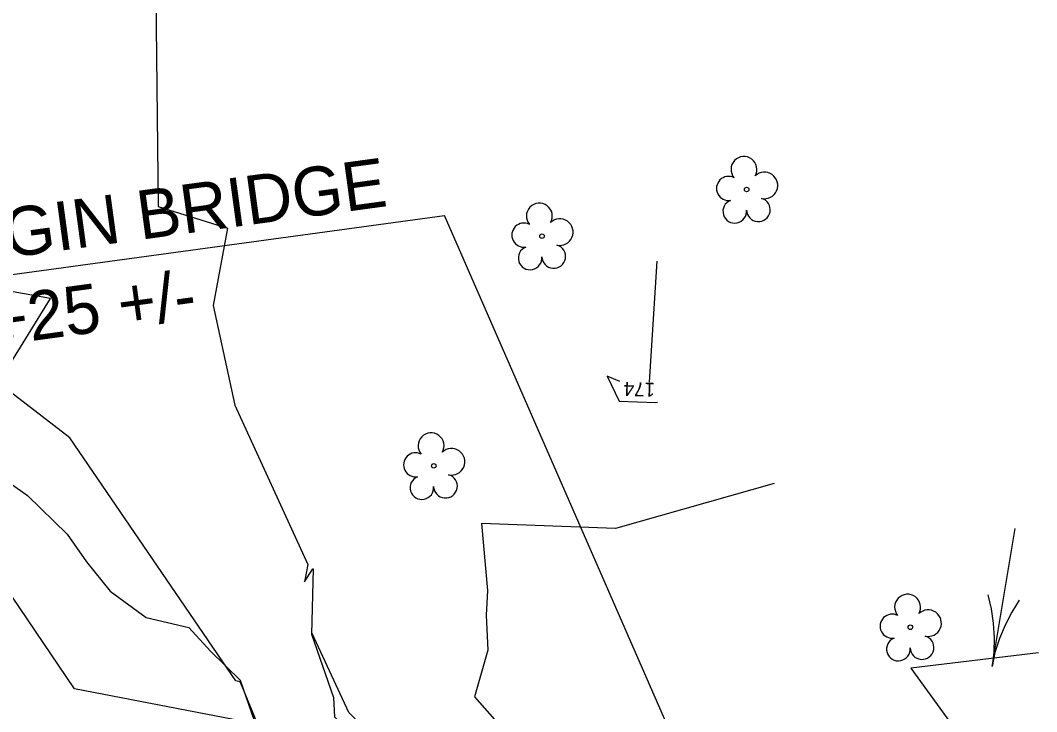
# Model space of a CAD drawing. Extents: x 2086416 to 2115205, y 575507 to 632762.
# Drawn here: x 2111920.5 to 2112066, y 581787.3 to 581886.3 of the extents above; entities that cross this region are included whole.
import ezdxf

# ---------------------------------------------------------------- set-up
doc = ezdxf.new("R2010")
doc.units = 0
for name, color, linetype in [('DTM Contours Minor', 7, 'Continuous'), ('DTM Contours Minor Text', 7, 'Continuous'), ('Exist Hydro River Flow Arrow CELL', 7, 'Continuous'), ('Exist Hydro Stream or Body of Water', 7, 'Continuous'), ('Exist Vegetation Tree CELL', 7, 'Continuous'), ('Prop Horizontal Alignment Station Label', 7, 'Continuous')]:
    doc.layers.add(name, color=color, linetype=linetype)

# ---------------------------------------------------------------- blocks, each defined once
blk = doc.blocks.new('EXIST VEGETATION TREE')
at = {"layer": 'Exist Vegetation Tree CELL'}
blk.add_line((0, 0), (0, 0), dxfattribs=at)
blk.add_circle((0, 0), 0.00652, dxfattribs=at)
for centre, radius, start, end in [((-0.0077, 0.0575), 0.0371, 330.1651, 219.7134), ((-0.0521, 0.0031), 0.0345, 62.6636, 279.3457), ((0.051, 0.0118), 0.038, 257.1011, 134.1999), ((0.0335, -0.058), 0.034, 181.2822, 74.56), ((-0.0341, -0.0624), 0.0338, 111.5671, 6.231)]:
    blk.add_arc(centre, radius, start, end, dxfattribs=at)

msp = doc.modelspace()

# ---------------------------------------------------------------- linework, layer by layer
at = {"layer": 'DTM Contours Minor'}
for points in [[(2111986.57, 581903.53), (2111939.89, 581889.69), (2111940.22, 581859.65), (2111950.16, 581856.54), (2111948.11, 581845.47), (2111951.21, 581831.21), (2111961.67, 581808.41), (2111961.19, 581805.94), (2111962.39, 581807.77), (2111962.43, 581807.8), (2111962.19, 581798.43), (2111965.32, 581789.35), (2111965.47, 581786.59), (2111973.88, 581778.03), (2111977.11, 581774.63), (2111980.39, 581770.88), (2111987.46, 581769.35), (2111990.76, 581766.29)], [(2112011.63, 581851.85), (2112010.53, 581834.49)], [(2111965.16, 581748.51), (2111970.69, 581749.86), (2111976.47, 581749.51), (2111981.91, 581752.5), (2111983.32, 581753.31), (2111982.36, 581755.79), (2111980.14, 581760.97), (2111975.64, 581761.52), (2111969.46, 581763.24), (2111967.22, 581769.18), (2111966.98, 581769.81), (2111965.9, 581771.13), (2111955.64, 581782.68), (2111952.51, 581790.39), (2111952, 581791.62), (2111951.36, 581791.75), (2111927.6, 581826.56), (2111917.31, 581834.4), (2111924.82, 581846.5), (2111912.24, 581848.72), (2111889.78, 581833.71), (2111886.95, 581833.16), (2111879.3, 581820.3)], [(2112006.32, 581834.62), (2112004.52, 581835.36), (2112006.26, 581831.8), (2112011.5, 581831.6), (2112011.73, 581831.66)], [(2112028.44, 581819.99), (2112005.74, 581813.55), (2111986.52, 581814.28), (2111987.37, 581804.69), (2111987.18, 581801.17), (2111987.42, 581796.12), (2111985.53, 581789.47), (2111990.87, 581783.42)], [(2111872.65, 581745.71), (2111876.29, 581746.03), (2111892.64, 581747.28), (2111896.68, 581747.18), (2111903.16, 581748.2), (2111906.44, 581747.76), (2111910.2, 581745.85), (2111927.92, 581748.91), (2111939.7, 581750.88), (2111951.09, 581752.85), (2111957.32, 581753.9), (2111972.19, 581756.27), (2111962.31, 581758.92), (2111961.55, 581761.08), (2111960.4, 581763.71), (2111955.81, 581769.32), (2111952.04, 581783.78), (2111951.03, 581786.21), (2111928.27, 581790.63), (2111917.03, 581807.1), (2111909.85, 581812.57), (2111903.37, 581811.31)], [(2112066.28, 581795.74), (2112048, 581793.55), (2112061.06, 581775.54), (2112061.72, 581774.65), (2112054.08, 581764.55), (2112060.15, 581764.51), (2112053.46, 581749.4), (2112053.37, 581746.7), (2112053.2, 581742.71), (2112053.57, 581738.55), (2112056.36, 581729.73), (2112057.47, 581723.04), (2112058.24, 581720.01), (2112063.98, 581709.95), (2112064.08, 581709.79), (2112064.18, 581709.63), (2112064.52, 581708.58), (2112068.43, 581698.96)]]:
    msp.add_lwpolyline(points, dxfattribs=at)
at = {"layer": 'Exist Hydro River Flow Arrow CELL'}
for p, q in [((2112059.64, 581793.82), (2112062.93, 581813.55)), ((2112059.03, 581804.06), (2112059.49, 581802.07)), ((2112061.28, 581803.68), (2112061.28, 581803.68)), ((2112063.54, 581803.31), (2112062.45, 581801.57)), ((2112059.49, 581802.07), (2112059.8, 581800.01)), ((2112062.45, 581801.57), (2112061.5, 581799.73)), ((2112059.8, 581800.01), (2112059.93, 581797.93)), ((2112061.5, 581799.73), (2112060.7, 581797.8)), ((2112059.93, 581797.93), (2112059.9, 581795.85)), ((2112060.7, 581797.8), (2112060.05, 581795.83)), ((2112059.9, 581795.85), (2112059.64, 581793.82)), ((2112060.05, 581795.83), (2112059.64, 581793.82))]:
    msp.add_line(p, q, dxfattribs=at)
at = {"layer": 'Exist Hydro Stream or Body of Water'}
for points in [[(2111914.05, 581823.59), (2111921.52, 581818.26), (2111927.21, 581812.76), (2111929.98, 581808.81), (2111933.37, 581804.58), (2111938.52, 581800.81), (2111944.63, 581799.41), (2111947.75, 581796), (2111952.02, 581791.78)], [(2112059.94, 581700.98), (2112062.59, 581707.22), (2112055.44, 581716.4), (2112054.67, 581722.41), (2112052.26, 581739.2), (2112051.84, 581739.05), (2112049.8, 581742.56), (2112050.11, 581752.77), (2112039.24, 581754.19), (2112006.97, 581748.92), (2112002.42, 581748.72), (2111999.87, 581752.29), (2111991.63, 581772.37), (2111979.18, 581775.68), (2111967.53, 581787.22), (2111962.27, 581798.52)], [(2111979.59, 581759.49), (2111969.33, 581762.97), (2111966.87, 581769.78), (2111955.26, 581782.47), (2111952.02, 581791.78)]]:
    msp.add_lwpolyline(points, dxfattribs=at)
at = {"layer": 'Prop Horizontal Alignment Station Label'}
for p in [(2111851.3, 581840.64), (2112041.04, 581721.6)]:
    msp.add_line(p, (2111981.25, 581858.37), dxfattribs=at)

# ---------------------------------------------------------------- block references
at = {"layer": 'Exist Vegetation Tree CELL', "xscale": 50, "yscale": 50}
for p in [(2112024.5, 581862.08), (2111995.2, 581855.4), (2111979.7, 581822.52), (2112047.93, 581799.42)]:
    msp.add_blockref('EXIST VEGETATION TREE', p, dxfattribs=at)

# ---------------------------------------------------------------- texts
at = {"layer": 'DTM Contours Minor Text'}
msp.add_text('174', height=2, rotation=178.2142, dxfattribs=at).set_placement((2112011.4, 581834.4))
at = {"layer": 'Prop Horizontal Alignment Station Label'}
for s, p in [('BEGIN BRIDGE', (2111906.26, 581850.59)), (' -L- POT Sta. 19+25 +/-  ', (2111849.09, 581830.43))]:
    msp.add_text(s, height=7, rotation=7.771, dxfattribs=at).set_placement(p)

doc.saveas('drawing.dxf')
